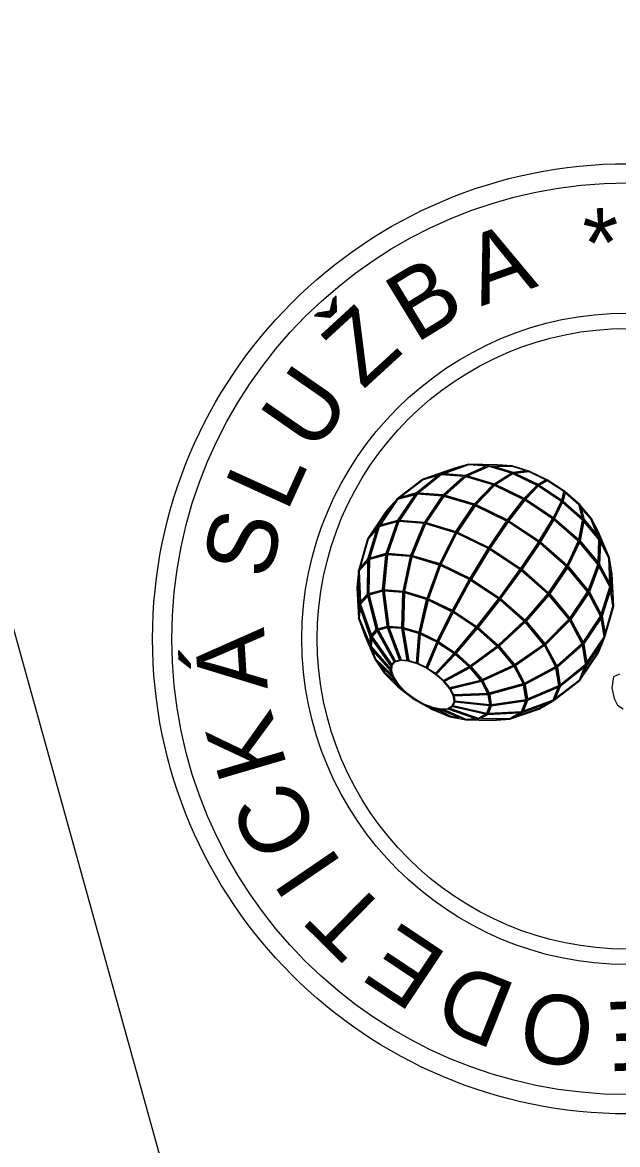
# Model space of a CAD drawing. Extents: x -821122 to -820555, y -1070892 to -1069801.
# Drawn here: x -820944.16 to -820934.49, y -1069908.99 to -1069890.77 of the extents above; entities that cross this region are included whole.
import ezdxf

# ---------------------------------------------------------------- set-up
doc = ezdxf.new("R2010")
doc.units = 0
doc.layers.add('Popisove_pole', color=7, linetype='Continuous')

msp = doc.modelspace()

# ---------------------------------------------------------------- linework, layer by layer
at = {"layer": 'Popisove_pole'}
for p, q in [((-820910.77, -1070021.294), (-820956.283, -1069857.5)), ((-820937.154, -1069898.025), (-820937.653, -1069898.199)), ((-820938.129, -1069901.408), (-820938.436, -1069901.114)), ((-820938.049, -1069901.524), (-820938.283, -1069901.337)), ((-820937.935, -1069901.641), (-820938.063, -1069901.56)), ((-820937.796, -1069901.747), (-820937.796, -1069901.764)), ((-820937.644, -1069901.834), (-820937.506, -1069901.931)), ((-820937.494, -1069901.893), (-820937.218, -1069902.045)), ((-820937.359, -1069901.92), (-820936.959, -1069902.097))]:
    msp.add_line(p, q, dxfattribs=at)
for points in [[(-820937.506, -1069901.931), (-820937.218, -1069902.045), (-820936.959, -1069902.097), (-820936.532, -1069902.106), (-820936.241, -1069902.084), (-820935.765, -1069901.921), (-820935.531, -1069901.784), (-820935.105, -1069901.455), (-820934.804, -1069901.01), (-820934.7, -1069900.754), (-820934.556, -1069900.25), (-820934.582, -1069899.728), (-820934.624, -1069899.468), (-820934.805, -1069899.044), (-820934.919, -1069898.828), (-820935.108, -1069898.603), (-820935.354, -1069898.386), (-820935.636, -1069898.199), (-820935.928, -1069898.057), (-820936.205, -1069897.973), (-820936.442, -1069897.955), (-820936.912, -1069897.945), (-820937.158, -1069898.014), (-820937.657, -1069898.187), (-820938.074, -1069898.509), (-820938.255, -1069898.713), (-820938.556, -1069899.158), (-820938.702, -1069899.674), (-820938.725, -1069899.951), (-820938.701, -1069900.448), (-820938.598, -1069900.731), (-820938.436, -1069901.114), (-820938.283, -1069901.337), (-820938.063, -1069901.56), (-820937.796, -1069901.764)], [(-820937.357, -1069898.117), (-820937.72, -1069898.409), (-820937.323, -1069898.44), (-820936.993, -1069898.146)], [(-820936.911, -1069897.958), (-820937.301, -1069898.097), (-820936.965, -1069898.123), (-820936.633, -1069897.979)], [(-820936.581, -1069897.984), (-820936.926, -1069898.133), (-820936.499, -1069898.263), (-820936.224, -1069898.092)], [(-820936.207, -1069897.985), (-820936.495, -1069897.984), (-820936.193, -1069898.075), (-820935.989, -1069898.051)], [(-820936.194, -1069898.102), (-820936.471, -1069898.275), (-820936.008, -1069898.5), (-820935.807, -1069898.29)], [(-820936.15, -1069898.096), (-820935.786, -1069898.273), (-820935.662, -1069898.2), (-820935.93, -1069898.07)], [(-820938.016, -1069898.48), (-820937.758, -1069898.408), (-820937.416, -1069898.133), (-820937.651, -1069898.198)], [(-820936.96, -1069898.149), (-820937.293, -1069898.448), (-820936.815, -1069898.592), (-820936.52, -1069898.283)], [(-820936.494, -1069898.292), (-820936.791, -1069898.603), (-820936.28, -1069898.851), (-820936.025, -1069898.52)], [(-820935.784, -1069898.303), (-820935.986, -1069898.513), (-820935.536, -1069898.813), (-820935.408, -1069898.553)], [(-820935.636, -1069898.214), (-820935.762, -1069898.287), (-820935.4, -1069898.528), (-820935.368, -1069898.392)], [(-820938.345, -1069898.933), (-820938.061, -1069898.854), (-820937.781, -1069898.441), (-820938.066, -1069898.52)], [(-820938.031, -1069898.854), (-820937.626, -1069898.885), (-820937.341, -1069898.464), (-820937.746, -1069898.432)], [(-820937.6, -1069898.891), (-820937.118, -1069899.037), (-820936.831, -1069898.614), (-820937.313, -1069898.468)], [(-820935.347, -1069898.409), (-820935.378, -1069898.544), (-820935.069, -1069898.816), (-820935.119, -1069898.609)], [(-820938.439, -1069899.007), (-820938.385, -1069898.946), (-820938.191, -1069898.66), (-820938.245, -1069898.721)], [(-820937.094, -1069899.047), (-820936.582, -1069899.296), (-820936.295, -1069898.872), (-820936.807, -1069898.623)], [(-820936.002, -1069898.532), (-820936.258, -1069898.864), (-820935.765, -1069899.192), (-820935.548, -1069898.835)], [(-820935.388, -1069898.569), (-820935.516, -1069898.828), (-820935.125, -1069899.171), (-820935.062, -1069898.856)], [(-820935.083, -1069898.652), (-820935.036, -1069898.845), (-820934.825, -1069899.099), (-820934.93, -1069898.835)], [(-820935.528, -1069898.85), (-820935.745, -1069899.207), (-820935.314, -1069899.585), (-820935.132, -1069899.198)], [(-820938.675, -1069899.625), (-820938.547, -1069899.48), (-820938.403, -1069899.005), (-820938.545, -1069899.165)], [(-820938.517, -1069899.468), (-820938.249, -1069899.393), (-820938.073, -1069898.883), (-820938.365, -1069898.964)], [(-820938.044, -1069898.878), (-820938.223, -1069899.393), (-820937.849, -1069899.421), (-820937.638, -1069898.909)], [(-820937.825, -1069899.427), (-820937.382, -1069899.561), (-820937.13, -1069899.059), (-820937.612, -1069898.913)], [(-820936.56, -1069899.308), (-820936.065, -1069899.638), (-820935.778, -1069899.213), (-820936.273, -1069898.884)], [(-820935.041, -1069898.879), (-820935.104, -1069899.191), (-820934.811, -1069899.542), (-820934.797, -1069899.171)], [(-820934.822, -1069899.038), (-820934.773, -1069899.162), (-820934.75, -1069899.205), (-820934.816, -1069899.049)], [(-820937.359, -1069899.57), (-820936.889, -1069899.798), (-820936.595, -1069899.317), (-820937.107, -1069899.068)], [(-820935.114, -1069899.218), (-820935.295, -1069899.604), (-820934.969, -1069899.995), (-820934.814, -1069899.577)], [(-820934.773, -1069899.214), (-820934.787, -1069899.572), (-820934.621, -1069899.883), (-820934.636, -1069899.471)], [(-820936.574, -1069899.329), (-820936.867, -1069899.811), (-820936.413, -1069900.113), (-820936.08, -1069899.658)], [(-820935.758, -1069899.229), (-820936.045, -1069899.653), (-820935.613, -1069900.032), (-820935.327, -1069899.608)], [(-820938.67, -1069900.186), (-820938.556, -1069900.057), (-820938.548, -1069899.519), (-820938.689, -1069899.678)], [(-820938.53, -1069900.045), (-820938.309, -1069899.984), (-820938.254, -1069899.421), (-820938.523, -1069899.495)], [(-820938.229, -1069899.417), (-820938.284, -1069899.982), (-820937.976, -1069900.006), (-820937.857, -1069899.446)], [(-820937.832, -1069899.451), (-820937.952, -1069900.01), (-820937.587, -1069900.121), (-820937.392, -1069899.584)], [(-820937.369, -1069899.593), (-820937.564, -1069900.13), (-820937.176, -1069900.318), (-820936.901, -1069899.82)], [(-820936.06, -1069899.673), (-820936.393, -1069900.128), (-820935.997, -1069900.476), (-820935.629, -1069900.052)], [(-820935.309, -1069899.627), (-820935.595, -1069900.05), (-820935.267, -1069900.444), (-820934.98, -1069900.02)], [(-820934.798, -1069899.605), (-820934.951, -1069900.018), (-820934.758, -1069900.381), (-820934.62, -1069899.938)], [(-820934.604, -1069899.668), (-820934.594, -1069899.936), (-820934.58, -1069900.027), (-820934.594, -1069899.729)], [(-820938.697, -1069900.257), (-820938.694, -1069900.217), (-820938.707, -1069899.882), (-820938.712, -1069899.951)], [(-820936.88, -1069899.833), (-820937.154, -1069900.331), (-820936.78, -1069900.58), (-820936.428, -1069900.133)], [(-820938.491, -1069900.722), (-820938.411, -1069900.631), (-820938.549, -1069900.088), (-820938.667, -1069900.221)], [(-820938.388, -1069900.619), (-820938.235, -1069900.577), (-820938.308, -1069900.009), (-820938.528, -1069900.07)], [(-820938.283, -1069900.007), (-820938.21, -1069900.574), (-820937.996, -1069900.591), (-820937.979, -1069900.031)], [(-820937.954, -1069900.036), (-820937.972, -1069900.595), (-820937.717, -1069900.672), (-820937.594, -1069900.145)], [(-820935.611, -1069900.07), (-820935.979, -1069900.494), (-820935.677, -1069900.856), (-820935.283, -1069900.464)], [(-820934.966, -1069900.044), (-820935.251, -1069900.465), (-820935.055, -1069900.835), (-820934.769, -1069900.413)], [(-820934.611, -1069899.992), (-820934.742, -1069900.415), (-820934.696, -1069900.696), (-820934.569, -1069900.249)], [(-820938.518, -1069900.858), (-820938.509, -1069900.748), (-820938.674, -1069900.277), (-820938.688, -1069900.446)], [(-820937.571, -1069900.154), (-820937.693, -1069900.681), (-820937.421, -1069900.813), (-820937.188, -1069900.341)], [(-820936.408, -1069900.148), (-820936.76, -1069900.595), (-820936.433, -1069900.882), (-820936.014, -1069900.494)], [(-820937.166, -1069900.353), (-820937.399, -1069900.826), (-820937.136, -1069901.001), (-820936.796, -1069900.599)], [(-820935.269, -1069900.485), (-820935.663, -1069900.876), (-820935.482, -1069901.217), (-820935.072, -1069900.856)], [(-820934.762, -1069900.447), (-820935.043, -1069900.862), (-820934.993, -1069901.166), (-820934.713, -1069900.751)], [(-820938.159, -1069901.196), (-820938.124, -1069901.156), (-820938.399, -1069900.656), (-820938.48, -1069900.747)], [(-820938.378, -1069900.642), (-820938.102, -1069901.143), (-820938.034, -1069901.124), (-820938.229, -1069900.601)], [(-820938.203, -1069900.6), (-820938.008, -1069901.121), (-820937.909, -1069901.128), (-820937.995, -1069900.616)], [(-820937.969, -1069900.622), (-820937.883, -1069901.132), (-820937.761, -1069901.169), (-820937.721, -1069900.697)], [(-820936.776, -1069900.615), (-820937.116, -1069901.016), (-820936.887, -1069901.218), (-820936.453, -1069900.898)], [(-820935.997, -1069900.512), (-820936.416, -1069900.9), (-820936.167, -1069901.198), (-820935.697, -1069900.872)], [(-820938.497, -1069900.907), (-820938.177, -1069901.272), (-820938.173, -1069901.22), (-820938.486, -1069900.781)], [(-820937.697, -1069900.707), (-820937.736, -1069901.178), (-820937.603, -1069901.243), (-820937.431, -1069900.836)], [(-820937.41, -1069900.849), (-820937.582, -1069901.255), (-820937.452, -1069901.341), (-820937.153, -1069901.02)], [(-820938.159, -1069901.362), (-820938.178, -1069901.308), (-820938.475, -1069900.969), (-820938.426, -1069901.107)], [(-820937.432, -1069901.357), (-820937.32, -1069901.455), (-820936.909, -1069901.231), (-820937.133, -1069901.035)], [(-820936.435, -1069900.916), (-820936.869, -1069901.236), (-820936.695, -1069901.444), (-820936.189, -1069901.21)], [(-820935.683, -1069900.892), (-820936.153, -1069901.219), (-820936.004, -1069901.499), (-820935.503, -1069901.231)], [(-820935.065, -1069900.883), (-820935.472, -1069901.241), (-820935.426, -1069901.526), (-820935.014, -1069901.194)], [(-820934.757, -1069900.86), (-820934.99, -1069901.205), (-820935.048, -1069901.348), (-820934.815, -1069901.004)], [(-820938.108, -1069901.461), (-820938.139, -1069901.416), (-820938.357, -1069901.207), (-820938.274, -1069901.328)], [(-820937.322, -1069901.47), (-820937.45, -1069901.358), (-820937.597, -1069901.26), (-820937.749, -1069901.186), (-820937.894, -1069901.142), (-820938.017, -1069901.133), (-820938.109, -1069901.158), (-820938.16, -1069901.216), (-820938.167, -1069901.302), (-820938.129, -1069901.408), (-820938.049, -1069901.524), (-820937.935, -1069901.641), (-820937.796, -1069901.747), (-820937.644, -1069901.834), (-820937.494, -1069901.893), (-820937.359, -1069901.92), (-820937.25, -1069901.912), (-820937.178, -1069901.87), (-820937.148, -1069901.797), (-820937.164, -1069901.7), (-820937.224, -1069901.588)], [(-820937.303, -1069901.474), (-820937.219, -1069901.574), (-820936.721, -1069901.452), (-820936.89, -1069901.25)], [(-820936.681, -1069901.465), (-820936.578, -1069901.66), (-820936.028, -1069901.508), (-820936.175, -1069901.231)], [(-820935.495, -1069901.256), (-820935.995, -1069901.523), (-820935.957, -1069901.758), (-820935.449, -1069901.541)], [(-820935.031, -1069901.239), (-820935.425, -1069901.557), (-820935.502, -1069901.746), (-820935.115, -1069901.447)], [(-820938.055, -1069901.551), (-820938.018, -1069901.574), (-820938.058, -1069901.533), (-820938.126, -1069901.479)], [(-820936.705, -1069901.474), (-820937.205, -1069901.596), (-820937.157, -1069901.687), (-820936.604, -1069901.663)], [(-820936.019, -1069901.532), (-820936.57, -1069901.684), (-820936.544, -1069901.847), (-820935.981, -1069901.765)], [(-820935.458, -1069901.572), (-820935.957, -1069901.785), (-820936.024, -1069901.95), (-820935.54, -1069901.774)], [(-820937.797, -1069901.748), (-820937.808, -1069901.74)], [(-820937.764, -1069901.769), (-820937.735, -1069901.785)], [(-820937.149, -1069901.712), (-820937.137, -1069901.786), (-820936.569, -1069901.847), (-820936.595, -1069901.688)], [(-820937.399, -1069901.96), (-820937.5, -1069901.905), (-820937.551, -1069901.884), (-820937.5, -1069901.92)], [(-820937.068, -1069902.063), (-820937.363, -1069901.932), (-820937.418, -1069901.921), (-820937.214, -1069902.033)], [(-820936.812, -1069902.074), (-820937.252, -1069901.925), (-820937.308, -1069901.929), (-820936.956, -1069902.084)], [(-820936.645, -1069902.006), (-820937.176, -1069901.883), (-820937.22, -1069901.909), (-820936.751, -1069902.068)], [(-820936.572, -1069901.871), (-820937.14, -1069901.81), (-820937.161, -1069901.861), (-820936.619, -1069901.986)], [(-820935.987, -1069901.791), (-820936.545, -1069901.872), (-820936.592, -1069901.987), (-820936.055, -1069901.959)], [(-820935.656, -1069901.843), (-820936.041, -1069901.982), (-820936.126, -1069902.032), (-820935.77, -1069901.909)], [(-820936.097, -1069901.986), (-820936.607, -1069902.013), (-820936.704, -1069902.069), (-820936.244, -1069902.072)]]:
    msp.add_lwpolyline(points, close=True, dxfattribs=at)
for points in [[(-820938.017, -1069901.133), (-820938.221, -1069900.586), (-820938.297, -1069899.993), (-820938.24, -1069899.404), (-820938.053, -1069898.865), (-820937.752, -1069898.419), (-820937.361, -1069898.105), (-820936.912, -1069897.945)], [(-820937.894, -1069901.142), (-820937.984, -1069900.604), (-820937.966, -1069900.019), (-820937.841, -1069899.435), (-820937.619, -1069898.898), (-820937.318, -1069898.453), (-820936.963, -1069898.135), (-820936.581, -1069897.971), (-820936.205, -1069897.973)], [(-820937.749, -1069901.186), (-820937.707, -1069900.688), (-820937.579, -1069900.136), (-820937.376, -1069899.576), (-820937.113, -1069899.052), (-820936.812, -1069898.607), (-820936.497, -1069898.277), (-820936.194, -1069898.088), (-820935.928, -1069898.057)], [(-820934.556, -1069900.25), (-820934.607, -1069899.937), (-820934.8, -1069899.575), (-820935.117, -1069899.195), (-820935.531, -1069898.831), (-820936.005, -1069898.515), (-820936.497, -1069898.277), (-820936.963, -1069898.135), (-820937.361, -1069898.105), (-820937.657, -1069898.187)], [(-820934.624, -1069899.468), (-820934.784, -1069899.167), (-820935.048, -1069898.851), (-820935.392, -1069898.549), (-820935.786, -1069898.287), (-820936.194, -1069898.088), (-820936.581, -1069897.971), (-820936.912, -1069897.945)], [(-820937.597, -1069901.26), (-820937.415, -1069900.83), (-820937.171, -1069900.335), (-820936.884, -1069899.815), (-820936.577, -1069899.312), (-820936.276, -1069898.867), (-820936.005, -1069898.515), (-820935.786, -1069898.287), (-820935.636, -1069898.199)], [(-820934.7, -1069900.754), (-820934.755, -1069900.414), (-820934.965, -1069900.019), (-820935.31, -1069899.606), (-820935.761, -1069899.21), (-820936.276, -1069898.867), (-820936.812, -1069898.607), (-820937.318, -1069898.453), (-820937.752, -1069898.419), (-820938.074, -1069898.509)], [(-820937.45, -1069901.358), (-820937.134, -1069901.017), (-820936.777, -1069900.597), (-820936.41, -1069900.13), (-820936.062, -1069899.655), (-820935.761, -1069899.21), (-820935.531, -1069898.831), (-820935.392, -1069898.549), (-820935.354, -1069898.386)], [(-820938.109, -1069901.158), (-820938.397, -1069900.635), (-820938.543, -1069900.062), (-820938.536, -1069899.486), (-820938.375, -1069898.954), (-820938.074, -1069898.509)], [(-820937.322, -1069901.47), (-820936.887, -1069901.234), (-820936.433, -1069900.899), (-820935.996, -1069900.494), (-820935.611, -1069900.051), (-820935.31, -1069899.606), (-820935.117, -1069899.195), (-820935.048, -1069898.851), (-820935.108, -1069898.603)], [(-820937.224, -1069901.588), (-820936.699, -1069901.46), (-820936.169, -1069901.215), (-820935.678, -1069900.874), (-820935.266, -1069900.464), (-820934.965, -1069900.019), (-820934.8, -1069899.575), (-820934.784, -1069899.167), (-820934.919, -1069898.828)], [(-820935.105, -1069901.455), (-820935.001, -1069901.199), (-820935.056, -1069900.859), (-820935.266, -1069900.464), (-820935.611, -1069900.051), (-820936.062, -1069899.655), (-820936.577, -1069899.312), (-820937.113, -1069899.052), (-820937.619, -1069898.898), (-820938.053, -1069898.865), (-820938.375, -1069898.954), (-820938.556, -1069899.158)], [(-820935.531, -1069901.784), (-820935.435, -1069901.549), (-820935.486, -1069901.236), (-820935.678, -1069900.874), (-820935.996, -1069900.494), (-820936.41, -1069900.13), (-820936.884, -1069899.815), (-820937.376, -1069899.576), (-820937.841, -1069899.435), (-820938.24, -1069899.404), (-820938.536, -1069899.486), (-820938.702, -1069899.674)], [(-820937.164, -1069901.7), (-820936.584, -1069901.675), (-820936.009, -1069901.516), (-820935.486, -1069901.236), (-820935.056, -1069900.859), (-820934.755, -1069900.414), (-820934.607, -1069899.937), (-820934.624, -1069899.468)], [(-820938.16, -1069901.216), (-820938.496, -1069900.746), (-820938.682, -1069900.218), (-820938.702, -1069899.674)], [(-820936.241, -1069902.084), (-820936.047, -1069901.971), (-820935.967, -1069901.776), (-820936.009, -1069901.516), (-820936.169, -1069901.215), (-820936.433, -1069900.899), (-820936.777, -1069900.597), (-820937.171, -1069900.335), (-820937.579, -1069900.136), (-820937.966, -1069900.019), (-820938.297, -1069899.993), (-820938.543, -1069900.062), (-820938.682, -1069900.218), (-820938.701, -1069900.448)], [(-820938.167, -1069901.302), (-820938.509, -1069900.911), (-820938.701, -1069900.448)], [(-820936.959, -1069902.097), (-820936.75, -1069902.082), (-820936.611, -1069902), (-820936.554, -1069901.861), (-820936.584, -1069901.675), (-820936.699, -1069901.46), (-820936.887, -1069901.234), (-820937.134, -1069901.017), (-820937.415, -1069900.83), (-820937.707, -1069900.688), (-820937.984, -1069900.604), (-820938.221, -1069900.586), (-820938.397, -1069900.635), (-820938.496, -1069900.746), (-820938.509, -1069900.911), (-820938.436, -1069901.114)], [(-820937.148, -1069901.797), (-820936.554, -1069901.861), (-820935.967, -1069901.776), (-820935.435, -1069901.549), (-820935.001, -1069901.199), (-820934.7, -1069900.754)], [(-820934.462, -1069901.356), (-820934.559, -1069901.397), (-820934.587, -1069901.579), (-820934.551, -1069901.752), (-820934.496, -1069901.859), (-820934.405, -1069901.918)], [(-820937.25, -1069901.912), (-820936.75, -1069902.082), (-820936.241, -1069902.084)], [(-820937.178, -1069901.87), (-820936.611, -1069902), (-820936.047, -1069901.971), (-820935.531, -1069901.784)]]:
    msp.add_lwpolyline(points, dxfattribs=at)
for radius in [7.713, 7.4, 7.4, 5.289, 5.289, 5.039]:
    msp.add_circle((-820934.331, -1069900.781), radius, dxfattribs=at)

# ---------------------------------------------------------------- texts
for s, rotation, p in [('*', 2.5185, (-820935.027, -1069894.926)), ('A', 19.5454, (-820936.711, -1069895.386)), ('B', 31.4663, (-820937.774, -1069895.994)), ('Ž', 42.5327, (-820938.629, -1069896.744)), ('U', 55.2976, (-820939.415, -1069897.793)), ('L', 65.52, (-820939.865, -1069898.743)), ('S', 76.5864, (-820940.153, -1069899.843)), ('Á', 93.6133, (-820940.173, -1069901.589)), ('K', 106.3781, (-820939.85, -1069902.859)), ('C', 118.299, (-820939.302, -1069903.954)), ('I', 124.2595, (-820938.945, -1069904.453)), ('T', 135.3259, (-820938.155, -1069905.271)), ('E', 146.3923, (-820937.222, -1069905.921)), ('D', 158.3132, (-820936.098, -1069906.407)), ('O', 171.0781, (-820934.811, -1069906.659)), ('E', 182.1445, (-820933.674, -1069906.642))]:
    msp.add_text(s, height=1.125, rotation=rotation, dxfattribs=at).set_placement(p)

doc.saveas('drawing.dxf')
